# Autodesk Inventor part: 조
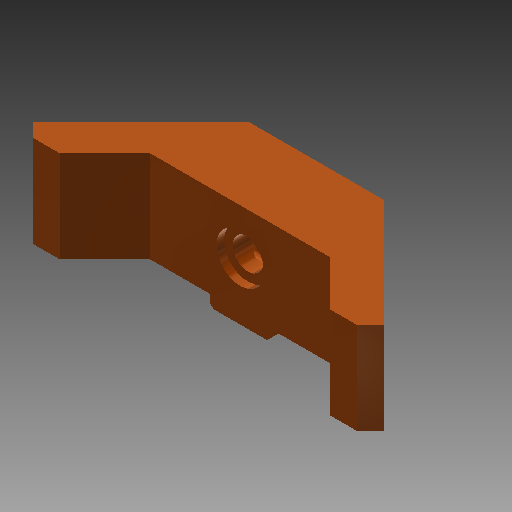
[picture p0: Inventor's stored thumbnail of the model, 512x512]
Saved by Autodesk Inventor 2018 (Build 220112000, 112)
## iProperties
Created: 2019-04
Part Number: 조
Material: 알루미늄 6061
Document SubType Name: Modeling
Designer: mduedu
Density: 1 g/cm^3
Appearance: 매끄러움 - 연한 주황색
Author: mduedu
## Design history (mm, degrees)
sketch "스케치1"
  geometry: L1 (45.962, 0)-(0, -45.962); L2 (0, -45.962)-(-45.962, 0); L3 (-45.962, 0)-(0, 45.962); L4 (0, 45.962)-(45.962, 0); L5 (45.962, 0)-(-45.962, 0); L6 (0, -45.962)-(0, 45.962); 1 further point
  constraints: 12 end point, 2 midpoint, 2 parallel, 2 perpendicular, 1 horizontal
  dimensions: "d0" = 65 distance of L1.end L2.end
extrude "돌출1" new body sketch "스케치1" distance "d2" = 27; taper "d3" = 0 deg
chamfer "모따기1" distance "d4" = 25; stored, may be unused: second distance "d5" = 2, angle "d6" = 45 deg
sketch "스케치2"
  geometry: L1 (-17.678, 28.284)-(-45.962, 0) reference; L2 (-17.678, 28.284)-(17.678, 28.284) reference; L3 (45.962, 0)-(17.678, 28.284) reference; L4 (-45.962, 0)-(0, -45.962) reference; L5 (0, -45.962)-(45.962, 0) reference; L6 (-23.536, 8.284)-(23.536, 8.284); L7 (-23.536, 8.284)-(-38.891, -7.071); L8 (38.891, -7.071)-(23.536, 8.284); 1 further point
  constraints: 6 end point, 3 parallel, 2 point on line
  dimensions: "d7" = 20 distance between parallel lines of L6 L2; "d8" = 10 distance between parallel lines of L1 L7; "d9" = 10 distance between parallel lines of L3 L8
extrude "돌출2" cut sketch "스케치2" extent not by distance; stored distance "d10" = 27; taper "d11" = 0 deg
sketch "스케치3"
  geometry: L1 (63.64, -27)-(63.64, 0) reference; L2 (56.569, -27)-(63.64, -27) reference; L3 (-28.284, -27)-(-28.284, 0) reference; L4 (-28.284, -27)-(-21.213, -27) reference; L5 (63.64, -27)-(25.678, -27); L6 (25.678, -27)-(25.678, -24); L7 (25.678, -24)-(63.64, -24); L8 (63.64, -24)-(63.64, -27); L9 (-28.284, -27)-(9.678, -27); L10 (9.678, -27)-(9.678, -24); L11 (9.678, -24)-(-28.284, -24); L12 (-28.284, -24)-(-28.284, -27); L13 (41.213, 0)-(-5.858, 0) reference; L14 (17.678, -27)-(17.678, 0)
  constraints: 18 end point, 4 parallel, 2 horizontal, 2 perpendicular, 1 midpoint, 1 symmetric about line
  dimensions: "d12" = 3 distance between parallel lines of L5 L7; "d14" = 16 distance between parallel lines of L10 L6
extrude "돌출3" cut sketch "스케치3" extent not by distance; stored distance "d15" = 27; taper "d16" = 0 deg
sketch "스케치4"
  geometry: L1 (31.536, -27)-(15.536, -27) reference; L2 (31.536, -24)-(47.071, -24) reference; 3 further points
  constraints: 1 midpoint, 1 vertical alignment
  dimensions: "d17" = 12 distance from line of L2 point (23.536, -12)
hole "구멍1" sketch "스케치4" at (23.536, -12) diameter "d18" = 8; stored, may be unused: countersink angle "d22" = 90 deg, drill point angle "d24" = 118 deg; dims "d19" = 6, "d20" = 12.5, "d21" = 2, "d23" = 14
node "작업 평면1"
sketch "스케치5"
  geometry: L1 (0, -15)-(0, 0); L2 (-50, -4)-(50, -4); L3 (50, -4)-(50, -1.75); L4 (-50, -1.75)-(-50, -4); L5 (12, -1.75)-(12, -2.75); L6 (12, -2.75)-(-12, -2.75); L7 (-12, -2.75)-(-12, -1.75); L8 (50, -1.75)-(12, -1.75); L9 (-12, -1.75)-(-50, -1.75); C1 r 4 at (0, 0) reference; 2 further points
  constraints: 18 end point, 4 parallel, 2 midpoint, 2 vertical, 2 vertical alignment, 1 collinear, 1 horizontal, 1 perpendicular, 1 tangent
  dimensions: "d26" = 2.5 diameter of L6 L2; "d28" = 4.5 diameter of L8 L2; "d29" = 24 distance of L5.end L6.end; "d30" = 100 distance between parallel lines of L3 L4
revolve "회전1" sketch "스케치5" stored, may be unused: angle "d31" = 90 deg
chamfer "모따기2" distance "d32" = 5; stored, may be unused: second distance "d33" = 2, angle "d34" = 45 deg
chamfer "모따기3" distance "d35" = 1; stored, may be unused: second distance "d36" = 2, angle "d37" = 45 deg
node "솔리드1"
other parameters: "d25" = -5
